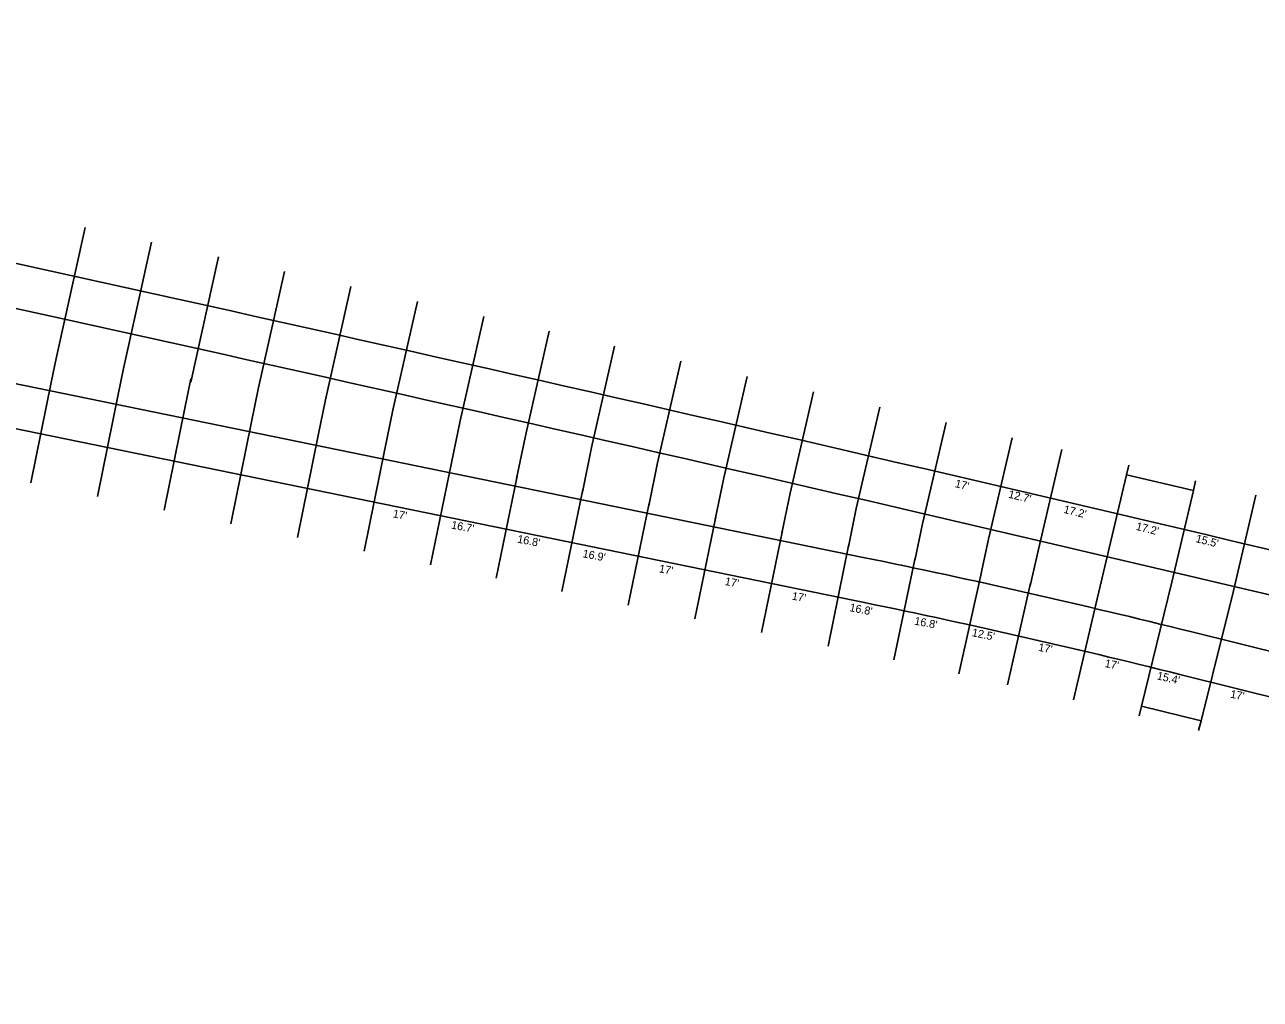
# Model space of a CAD drawing. Extents: x 4995357 to 4999033, y 3881202 to 3881750.
# Drawn here: x 4997956.4 to 4998265.1, y 3881415.4 to 3881658.9 of the extents above; entities that cross this region are included whole.
import ezdxf

# ---------------------------------------------------------------- set-up
doc = ezdxf.new("R2010")
doc.units = 0
for name, color, linetype in [('dsn3DCenterLine', 7, 'Continuous'), ('dsn3DCurbFormgrade', 7, 'Continuous'), ('dsn3DCurbTop', 7, 'Continuous'), ('dsn3DDNC', 7, 'Continuous'), ('dsn3DExistingPvmtBtm', 7, 'Continuous')]:
    doc.layers.add(name, color=color, linetype=linetype)

msp = doc.modelspace()

# ---------------------------------------------------------------- linework, layer by layer
at = {"layer": 'dsn3DCurbFormgrade'}
for p, q in [((4997963.11, 3881569.95), (4997957.89, 3881544.48)), ((4997979.76, 3881566.54), (4997974.54, 3881541.07)), ((4997996.42, 3881563.12), (4997991.2, 3881537.65)), ((4998013.07, 3881559.71), (4998007.85, 3881534.24)), ((4998029.72, 3881556.3), (4998024.51, 3881530.83)), ((4998046.38, 3881552.89), (4998041.16, 3881527.42)), ((4998063.03, 3881549.47), (4998057.81, 3881524)), ((4998074.19, 3881520.65), (4998079.41, 3881546.12)), ((4998090.62, 3881517.28), (4998095.83, 3881542.75)), ((4998107.2, 3881513.88), (4998112.42, 3881539.36)), ((4998123.84, 3881510.48), (4998129.05, 3881535.95)), ((4998140.47, 3881507.07), (4998145.69, 3881532.54)), ((4998157.11, 3881503.66), (4998162.33, 3881529.13)), ((4998173.51, 3881500.26), (4998178.89, 3881525.69)), ((4998189.81, 3881496.73), (4998195.41, 3881522.12)), ((4998201.97, 3881494.01), (4998207.73, 3881519.37)), ((4998218.41, 3881490.21), (4998224.38, 3881515.51)), ((4998241, 3881511.51), (4998235.41, 3881488.69)), ((4998255.98, 3881507.79), (4998250.3, 3881485))]:
    msp.add_line(p, q, dxfattribs=at)
at = {"layer": 'dsn3DCurbTop'}
for p, q in [((4997971.48, 3881608.27), (4997964.26, 3881575.55)), ((4997988.09, 3881604.6), (4997981.08, 3881572.99)), ((4998004.82, 3881600.88), (4997997.86, 3881569.61)), ((4998021.3, 3881597.21), (4998014.73, 3881567.82)), ((4998037.89, 3881593.49), (4998031.55, 3881565.22)), ((4998054.49, 3881589.77), (4998048.37, 3881562.6)), ((4998071.07, 3881586.02), (4998065.18, 3881559.97)), ((4998087.39, 3881582.33), (4998081.64, 3881556.97)), ((4998103.76, 3881578.61), (4998097.99, 3881553.26)), ((4997963.11, 3881569.95), (4997964.26, 3881575.55)), ((4997979.76, 3881566.54), (4997981.08, 3881572.99)), ((4998120.29, 3881574.83), (4998114.49, 3881549.49)), ((4997996.42, 3881563.12), (4997997.91, 3881570.41)), ((4998136.87, 3881571.03), (4998131.05, 3881545.69)), ((4998013.07, 3881559.71), (4998014.73, 3881567.82)), ((4998153.45, 3881567.22), (4998147.61, 3881541.89)), ((4998031.55, 3881565.22), (4998029.72, 3881556.3)), ((4998170.03, 3881563.39), (4998164.16, 3881538.06)), ((4998046.38, 3881552.89), (4998048.37, 3881562.6)), ((4998063.03, 3881549.47), (4998065.18, 3881559.97)), ((4998079.29, 3881545.51), (4998081.64, 3881556.97)), ((4998186.58, 3881559.56), (4998180.7, 3881534.23)), ((4998203.14, 3881555.7), (4998197.23, 3881530.38)), ((4998095.71, 3881542.14), (4998097.99, 3881553.26)), ((4998215.49, 3881552.82), (4998209.57, 3881527.5)), ((4998112.29, 3881538.74), (4998114.49, 3881549.49)), ((4998128.93, 3881535.33), (4998131.05, 3881545.69)), ((4998231.66, 3881546.46), (4998226.29, 3881523.58)), ((4998145.57, 3881531.92), (4998147.61, 3881541.89)), ((4998248.39, 3881542.53), (4998243, 3881519.65)), ((4998264.03, 3881541.4), (4998258.05, 3881516.1)), ((4998162.21, 3881528.51), (4998164.16, 3881538.06)), ((4998178.76, 3881525.08), (4998180.7, 3881534.23)), ((4998195.28, 3881521.51), (4998197.23, 3881530.38)), ((4998207.59, 3881518.76), (4998209.57, 3881527.5)), ((4998224.38, 3881515.51), (4998226.29, 3881523.58)), ((4998243, 3881519.65), (4998241, 3881511.51)), ((4998258.05, 3881516.1), (4998255.98, 3881507.79))]:
    msp.add_line(p, q, dxfattribs=at)
at = {"layer": 'dsn3DDNC'}
for p, q in [((4997658.03, 3881629.91), (4998165.9, 3881525.84)), ((4997655.82, 3881619.13), (4998163.69, 3881515.07)), ((4998247.68, 3881507.29), (4998573.41, 3881426.12)), ((4998245.02, 3881496.61), (4998570.75, 3881415.45))]:
    msp.add_line(p, q, dxfattribs=at)
for centre, radius, start, end in [((4993658.81, 3862065.98), 20000, 76.008501, 78.420039), ((4993658.81, 3862065.98), 19989, 76.008501, 78.420039), ((4997765.94, 3879573.9), 1992.5, 76.0085, 78.42004), ((4997765.94, 3879573.9), 1981.5, 76.0085, 78.42004)]:
    msp.add_arc(centre, radius, start, end, dxfattribs=at)
at = {"layer": 'dsn3DExistingPvmtBtm'}
for p, q in [((4998232.23, 3881548.9), (4998231.66, 3881546.46)), ((4998231.66, 3881546.46), (4998248.39, 3881542.53)), ((4998248.96, 3881544.96), (4998248.39, 3881542.53))]:
    msp.add_line(p, q, dxfattribs=at)
msp.add_lwpolyline([(4998234.81, 3881486.27), (4998235.41, 3881488.69), (4998250.3, 3881485), (4998249.7, 3881482.57)], dxfattribs=at)

# ---------------------------------------------------------------- texts
at = {"layer": 'dsn3DCenterLine'}
for s, rotation, p in [("17'", 345.9626, (4998188.69, 3881543.42)), ("12.7'", 345.9626, (4998202.02, 3881540.78)), ("17.2'", 345.9626, (4998215.82, 3881536.98)), ("17'", 349.171, (4998048.25, 3881535.85)), ("16.7'", 349.171, (4998062.83, 3881533.06)), ("17.2'", 345.9626, (4998233.9, 3881532.73)), ("16.8'", 349.171, (4998079.34, 3881529.54)), ("15.5'", 345.9626, (4998248.83, 3881529.67)), ("16.9'", 349.171, (4998095.67, 3881525.89)), ("17'", 349.171, (4998114.75, 3881522.13)), ("17'", 349.171, (4998131.2, 3881518.96)), ("17'", 349.171, (4998147.95, 3881515.32)), ("16.8'", 349.171, (4998162.36, 3881512.42)), ("16.8'", 349.171, (4998178.56, 3881509.06)), ("12.5'", 348.348, (4998192.93, 3881506.18)), ("17'", 349.171, (4998209.54, 3881502.5)), ("17'", 349.171, (4998226.14, 3881498.46)), ("15.4'", 346.7823, (4998239.15, 3881495.4)), ("17'", 349.171, (4998257.5, 3881490.81))]:
    msp.add_text(s, height=2, rotation=rotation, dxfattribs=at).set_placement(p)

doc.saveas('drawing.dxf')
